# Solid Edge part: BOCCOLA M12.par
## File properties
Subject: BOCCOLA M12
Author: f_grande
Template: Normal.par
Last saved by: Francesco
Revision: 2
Application: Solid Edge
Material: Acciaio
Stile della faccia: Acciaio
Stile di riempimento: ANSI32(Acciaio)
Stile virtuale: Acciaio lavorato a macchina
Coef. of Thermal Exp: 0.0
Thermal Conductivity: 32.0
Specific Heat: 481.0
Modulus of Elasticity: 199947953000.0
Poisson's Ratio: 0.29
Yield Stress: 262000766.0
Ultimate Stress: 358527364.0
Elongation: 0.0
Tipo di contenuto documento: 0
Densità: 7833,000 kg/m^3
Precisione: 0,990
Document Number: KR0107
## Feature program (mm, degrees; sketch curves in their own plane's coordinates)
sketch for "unnamed Protrusion 1" #1 plane through (0, 0, 0) normal (0, -1, 0) x-axis (1, 0, 0)
  circle centre (0, 0) radius 5
sketch for "unnamed Protrusion 1" #2 plane through (0, 0, 0) normal (0, -1, 0) x-axis (1, 0, 0)
  circle centre (0, 0) radius 10
extrude "unnamed Protrusion 1" add finite 8 along +normal
chamfer "Smusso_1" setback 3
thread "unnamed Thread 1"
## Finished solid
Body 1: solid body, 5 faces, 5 edges, 0 vertices.
  Faces by surface: cylinder 2, plane 2, cone 1
  Edges by curve: circle 5
Bounding box of the edges (mm): 20.000 x 8.000 x 20.000, from (-10, -8, -10) to (10, 0, 10).
Cylindrical faces by radius (mm): R5 x1, R10 x1
Conical faces (half-angle, radius in mm at the cone's reference point): 45 deg R10 x1
Planar faces by outward normal: +y 1, -y 1
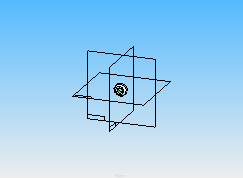
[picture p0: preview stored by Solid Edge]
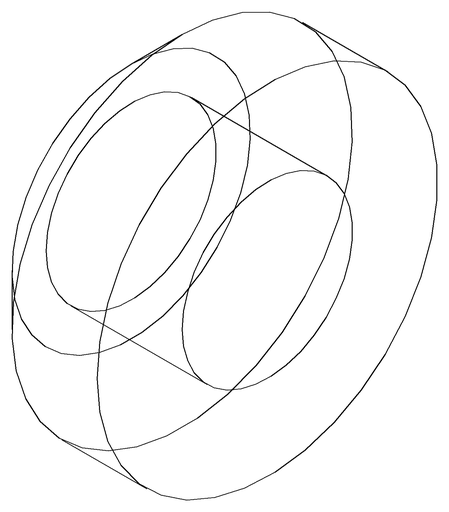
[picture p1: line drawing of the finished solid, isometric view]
